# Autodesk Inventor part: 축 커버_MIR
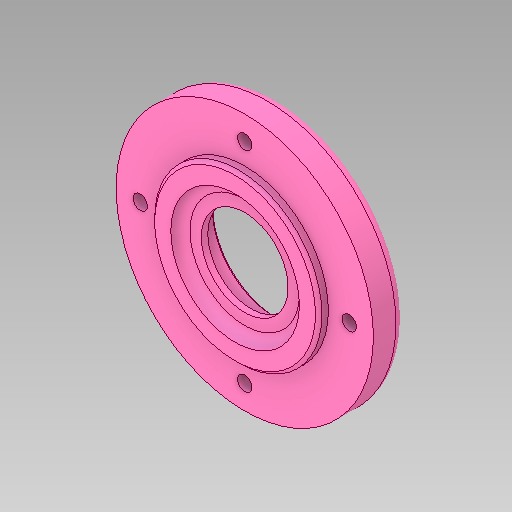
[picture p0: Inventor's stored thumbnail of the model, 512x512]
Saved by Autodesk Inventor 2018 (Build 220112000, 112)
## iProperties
Created: 2015-10
Part Number: 축 커버_MIR
Material: 강철, 연강
Document SubType Name: Modeling
Designer: home
Density: 7.86 g/cm^3
Appearance: 강철
Author: mdu
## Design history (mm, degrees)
derived "축 커버.ipt"
  sketch "스케치1"
    geometry: C1 r 40 at (0, 0) reference; C2 r 26 at (0, 0) reference; 1 further point
    dimensions: "d0" = 10 dimension on point (0, 0) C1.centre C1 C2.centre C2
  sketch "스케치2"
    geometry: C1 r 20 at (0, 0) reference; 1 further point
    dimensions: "d0" = 10 dimension on point (0, 0) C1.centre C1
  sketch "스케치3"
    geometry: C1 r 1.621 at (0, 32.5) reference; 1 further point
    dimensions: "d0" = 10 dimension on point (0, 0) C1.centre C1
feature "솔리드1::축 커버.ipt"
tag "피쳐 태그1"
node "솔리드1"
